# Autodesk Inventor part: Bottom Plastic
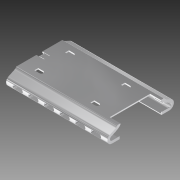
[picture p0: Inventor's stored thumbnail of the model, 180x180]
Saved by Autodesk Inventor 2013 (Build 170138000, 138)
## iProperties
Company: Autodesk Inc.
Created: 2005-12
Document SubType Name: Modeling
Density: 1 g/cm^3
Mass: 594.642 g
Surface Area: 3246.47 cm^2
Volume: 594.642 cm^3
Material: Allgemein
Author: Autodesk Inc.
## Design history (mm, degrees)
workplane "Work Plane1"
sketch "Sketch9"
  geometry: L1 (-52, 89)-(-52, -89); L2 (-52, 89)-(-52, 90); L3 (-52, -89)-(-52, -90); L4 (-44.026, 98.78)-(-34.314, 119.607); L5 (0, 112)-(0, 82); L6 (-18, 130)-(13.521, 130); L7 (-52, 0)-(18.088, 0); L8 (-44.026, -98.78)-(-34.314, -119.607); L9 (0, -112)-(0, -82); L10 (-18, -130)-(13.521, -130); L11 (0, 82)-(0, -82); A1 r 20 centre (-62.152, 107.232) between (-52, 90) and (-44.026, 98.78); A2 r 18 centre (-18, 112) between (0, 112) and (-34.314, 119.607); A3 r 20 centre (-62.152, -107.232) between (-44.026, -98.78) and (-52, -90); A4 r 18 centre (-18, -112) between (-34.314, -119.607) and (0, -112); 3 further points
  constraints: 22 end point, 10 point on circle, 8 symmetric about line, 4 centre point, 4 tangent, 3 collinear, 3 midpoint, 2 parallel, 2 perpendicular, 1 coincident, 1 horizontal, 2 other
  dimensions: "d49" = 1 distance of L1.start L2.end; "d50" = 40 distance from line of L2.end L6; "d51" = 52 distance between parallel lines of L5 L2; "d52" = 155 deg angle of L1 L4; "d53" = 20 radius of A1; "d54" = 18 radius of A2; "d55" = 30 distance of L5.start L5.end; "d134" = 178 distance of L1.start L1.end
extrude "Extrusion8" new body sketch "Sketch9" distance "d56" = 396; taper "d57" = 0 deg
workplane "Work Plane3"
sketch "Sketch3"
  geometry: L1 (-32.5, -24.657)-(-57.5, -24.657); L2 (-57.5, -24.657)-(-57.5, -9.657); L3 (-57.5, -9.657)-(-32.5, -9.657); L4 (-32.5, -9.657)-(-32.5, -24.657); L5 (0, -34.314)-(-396, -34.314); L6 (0, 0)-(-396, 0); L7 (0, -34.314)-(0, 0); 3 further points
  constraints: 14 end point, 3 midpoint, 2 parallel, 2 perpendicular, 2 vertical alignment, 1 horizontal alignment, 4 other
  dimensions: "d13" = 25 distance of L2.end L3.end; "d15" = 15 distance between parallel lines of L3 L1
extrude "Extrusion2" cut sketch "Sketch3" distance "d17" = 15; taper "d18" = 0 deg
mirror "Mirror4"
pattern_linear "Rectangular Pattern3" dims "d65" = 306 (computed from d58)
shell "Shell3" dims "d66" = 5, "d67" = 3, "d71" = 2
sketch "Sketch10"
  geometry: L1 (-44.026, -98.78)-(-34.314, -119.607) reference; L2 (0, -112)-(0, 112) reference; L3 (-34.314, 119.607)-(-44.026, 98.78) reference; L4 (-33.595, 97.486)-(-25.25, 115.381); L5 (-10, 112)-(-10, -112); L6 (-25.25, -115.381)-(-33.595, -97.486); L7 (-52, 90)-(-52, -90) reference; L8 (-52, 79.012)-(-47, 79.012); L9 (-52, -79.012)-(-47, -79.012); A1 r 18 centre (-18, -112) between (-34.314, -119.607) and (0, -112) reference; A2 r 18 centre (-18, 112) between (0, 112) and (-34.314, 119.607) reference; A3 r 8 centre (-18, 112) between (-10, 112) and (-25.25, 115.381); A4 r 8 centre (-18, -112) between (-25.25, -115.381) and (-10, -112); A5 r 60 centre (-87.973, 122.843) between (-47, 79.012) and (-33.595, 97.486); A6 r 60 centre (-87.973, -122.843) between (-33.595, -97.486) and (-47, -79.012)
  constraints: 10 end point, 8 point on circle, 4 centre point, 2 parallel, 2 point on line, 2 tangent, 1 equal radius, 1 perpendicular, 4 other
  dimensions: "d68" = 10 radial gap between concentric circles of A2 A3; "d124" = 5 distance of L8.start L8.end; "d125" = 60 radius of A5; "d126" = 10.988 distance from line of L8 L7.start; "d127" = 10.988 distance from line of L7.end L9 (derived)
extrude "Extrusion9" cut sketch "Sketch10" distance "d69" = 2; taper "d70" = 0 deg
sketch "Sketch11"
  geometry: L1 (-94.553, -34.962)-(-115.381, -25.25); L2 (-112, -10)-(112, -10); L3 (115.381, -25.25)-(94.553, -34.962); L4 (81.339, -47)-(-81.339, -47); A1 r 20 centre (-107.232, -62.152) between (-90, -52) and (-98.78, -44.026); A2 r 30 centre (-107.232, -62.152) between (-81.339, -47) and (-94.553, -34.962); A3 r 8 centre (-112, -18) between (-112, -10) and (-115.381, -25.25); A4 r 8 centre (112, -18) between (115.381, -25.25) and (112, -10); A5 r 30 centre (107.232, -62.152) between (94.553, -34.962) and (81.339, -47)
  constraints: 11 point on circle, 8 end point, 5 centre point, 1 parallel
extrude "Extrusion10" cut sketch "Sketch11" distance "d74" = 3; taper "d75" = 0 deg
sketch "Sketch12"
  geometry: L1 (0, 194)-(396, 194); L2 (396, 194)-(396, 30); L3 (396, 30)-(0, 30); L4 (0, 30)-(0, 194)
  constraints: 8 end point, 2 parallel, 1 horizontal, 1 perpendicular
extrude "Extrusion11" cut sketch "Sketch12" distance "d78" = 12; taper "d79" = 0 deg
workplane "Work Plane7"
sketch "Sketch14" dims "d97" = 10
  geometry: L1 (0, 15)-(396, 15); L2 (35, 20)-(55, 20); L3 (55, 20)-(55, 10); L4 (55, 10)-(35, 10); L5 (35, 10)-(35, 20); L6 (341, 20)-(361, 20); L7 (361, 20)-(361, 10); L8 (361, 10)-(341, 10); L9 (341, 10)-(341, 20); C1 r 5 at (341, 15); 3 further points
  constraints: 18 end point, 4 midpoint, 4 parallel, 3 vertical alignment, 2 horizontal, 2 perpendicular, 1 centre point, 1 collinear, 1 tangent, 9 other
  dimensions: "d96" = 20 distance of L2.start L2.end
extrude "Extrusion12" join sketch "Sketch14" distance "d98" = 0.5; taper "d99" = 0 deg
mirror "Mirror6"
sketch "Sketch15" dims "d104" = 15
  geometry: L1 (0, -78.5)-(30, -78.5); L2 (30, -78.5)-(30, -101.5); L3 (30, -101.5)-(0, -101.5); L4 (0, -101.5)-(0, -78.5); L5 (48, -22.5)-(68, -22.5); L6 (68, -22.5)-(68, -37.5); L7 (68, -37.5)-(48, -37.5); L8 (48, -37.5)-(48, -22.5); L9 (48, -142.5)-(68, -142.5); L10 (68, -142.5)-(68, -157.5); L11 (68, -157.5)-(48, -157.5); L12 (48, -157.5)-(48, -142.5); L13 (267, -22.5)-(287, -22.5); L14 (287, -22.5)-(287, -37.5); L15 (287, -37.5)-(267, -37.5); L16 (267, -37.5)-(267, -22.5); L17 (267, -142.5)-(287, -142.5); L18 (287, -142.5)-(287, -157.5); L19 (287, -157.5)-(267, -157.5); L20 (267, -157.5)-(267, -142.5); L21 (359, 369)-(359, 369); L22 (277, -22.5)-(277, -37.5); L23 (58, -22.5)-(58, -37.5); 4 further points
  constraints: 46 end point, 10 parallel, 8 midpoint, 5 horizontal, 5 perpendicular, 4 vertical alignment, 3 collinear, 3 equal length, 8 other
  dimensions: "d102" = 120 distance of point (68, -150) point (68, -30); "d103" = 20 distance of L10.end L11.end; "d105" = 30 distance of L1.start L1.end; "d106" = 23 distance of L1.end L2.end
extrude "Extrusion13" cut sketch "Sketch15" distance "d107" = 5; taper "d108" = 0 deg
sketch "Sketch16"
  geometry: L1 (0, 180)-(0, 101.5); L2 (30, 100)-(10.2, 100); L3 (10.2, 100)-(10.2, 80); L4 (10.2, 80)-(30, 80); L5 (30, 80)-(30, 100); L6 (30, 101.5)-(30, 78.5) reference; 1 further point
  constraints: 10 end point, 2 midpoint, 2 parallel, 1 horizontal, 1 perpendicular
  dimensions: "d109" = 20 distance of L2.end L3.end; "d110" = 10.2 distance between parallel lines of L3 L1
extrude "Extrusion14" join sketch "Sketch16" distance "d111" = 3; taper "d112" = 0 deg
sketch "Sketch18" dims "d113" = 2.5
  geometry: L1 (0, 0)-(19.8, 0) reference; 1 further point
  constraints: 1 horizontal alignment, 1 point on line, 2 other
extrude "Extrusion15" join sketch "Sketch18" stored distance "d114" = 5; taper "d115" = 0 deg
sketch "Sketch22"
  geometry: L1 (394, 10.988)-(392, 10.988); L2 (-2, 169.012)-(0, 169.012); L3 (394, 169.012)-(354, 169.012); L4 (354, 169.012)-(354, 10.988); L5 (354, 10.988)-(394, 10.988); L6 (394, 10.988)-(394, 169.012); L7 (394, 10.988)-(394, 169.012) reference; 1 further point
  constraints: 12 end point, 2 collinear, 2 midpoint, 2 parallel, 1 horizontal, 1 perpendicular
  dimensions: "d138" = 158.024 distance of L3.end L4.end; "d139" = 40 distance of L4.end L5.end
extrude "Extrusion19" cut sketch "Sketch22" distance "d129" = 5; taper "d130" = 0 deg
body "Solid1"
fillet "Fillet1" dims "d140" = 2
other parameters: "d16" = 142 [user parameter], "d34" = 3, "d58" = 396 (derived), "d80" = 18, "d100" = 82, "d137" = 0
